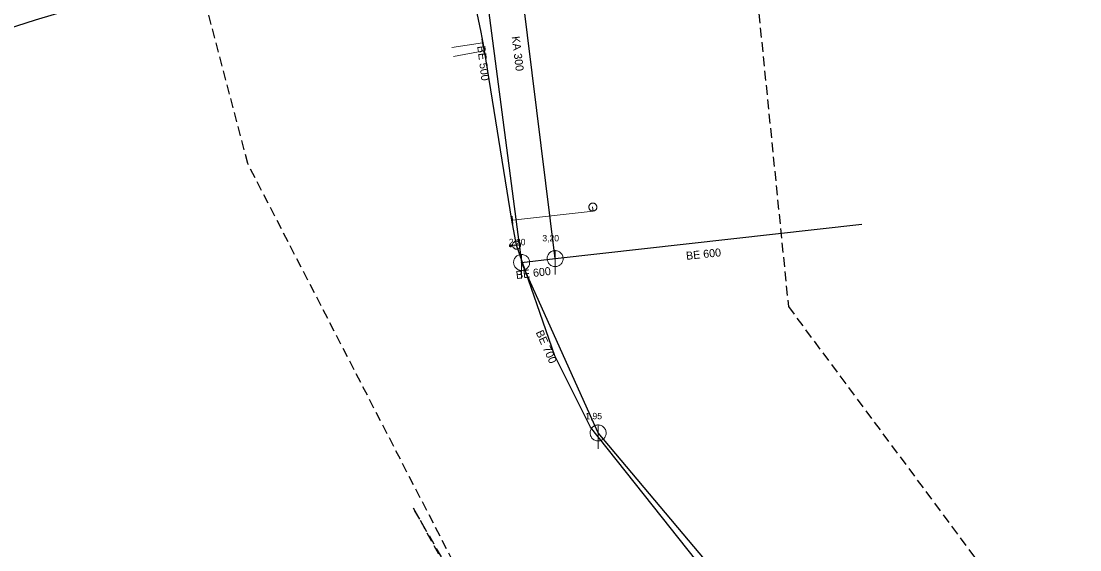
# Model space of a CAD drawing. Extents: x -689820 to -689363, y -975369 to -975062.
# Drawn here: x -689676.5 to -689544.2, y -975215.7 to -975149.6 of the extents above; entities that cross this region are included whole.
import ezdxf

# ---------------------------------------------------------------- set-up
doc = ezdxf.new("R2010")
doc.units = 0
doc.header["$LTSCALE"] = 0.4
doc.linetypes.add('MEDIUM_DASHED', pattern=[4.5, 3, -1.5])
doc.layers.add('1', color=7, linetype='Continuous')
for name, color, linetype, lineweight in [('13', 7, 'Continuous', 13), ('14', 7, 'Continuous', 25), ('17', 7, 'Continuous', 25), ('22', 7, 'Continuous', 13), ('23', 7, 'Continuous', 13), ('34', 7, 'Continuous', 13), ('47', 7, 'Continuous', 13), ('63', 7, 'MEDIUM_DASHED', 25), ('9', 7, 'Continuous', 13)]:
    doc.layers.add(name, color=color, linetype=linetype, lineweight=lineweight)

msp = doc.modelspace()

# ---------------------------------------------------------------- linework, layer by layer
at = {"layer": '13'}
for p, q in [((-689618.844, -975152.357), (-689622.676, -975152.926)), ((-689618.68, -975153.32), (-689622.456, -975154.063))]:
    msp.add_line(p, q, dxfattribs=at)
msp.add_lwpolyline([(-689615.092, -975174.481), (-689605.021, -975173.394), (-689605.076, -975172.838)], dxfattribs=at)
at = {"layer": '14'}
for p, q in [((-689609.76, -975179.3), (-689615.949, -975129.309)), ((-689620.329, -975131.18), (-689613.954, -975179.785)), ((-689609.76, -975179.3), (-689571.434, -975175.006)), ((-689613.954, -975179.785), (-689609.76, -975179.3)), ((-689604.392, -975201.087), (-689613.954, -975179.785)), ((-689553.342, -975261.657), (-689604.392, -975201.087))]:
    msp.add_line(p, q, dxfattribs=at)
at = {"layer": '14', "lineweight": 13}
for p, q in [((-689618.739, -975152.34), (-689618.844, -975152.357)), ((-689618.58, -975153.313), (-689618.68, -975153.32)), ((-689615.184, -975174.495), (-689615.092, -975174.481)), ((-689614.585, -975177.62), (-689615.339, -975177.698))]:
    msp.add_line(p, q, dxfattribs=at)
at = {"layer": '17'}
for points in [[(-689742.145, -975169.096), (-689736.511, -975167.526), (-689719.508, -975163.375), (-689716.769, -975162.653), (-689711.482, -975161.26), (-689710.52, -975160.971), (-689674.675, -975149.452), (-689666.449, -975146.987), (-689622.85, -975134.205)], [(-689614.585, -975177.62), (-689615.184, -975174.495), (-689618.58, -975153.313), (-689618.739, -975152.34), (-689619, -975151.02), (-689622.51, -975134.399)], [(-689545.213, -975278.312), (-689554.449, -975264.469), (-689605.354, -975200.364), (-689609.803, -975191.467), (-689614.585, -975177.62)]]:
    msp.add_lwpolyline(points, dxfattribs=at)
at = {"layer": '22'}
for p, q in [((-689609.76, -975181.3), (-689609.759, -975178.3)), ((-689613.954, -975181.785), (-689613.953, -975178.785)), ((-689604.392, -975203.087), (-689604.391, -975200.087))]:
    msp.add_line(p, q, dxfattribs=at)
for points in [[(-689608.76, -975179.3), (-689608.765, -975179.191), (-689608.783, -975179.083), (-689608.813, -975178.977), (-689608.853, -975178.876), (-689608.905, -975178.779), (-689608.967, -975178.689), (-689609.039, -975178.606), (-689609.119, -975178.532), (-689609.207, -975178.466), (-689609.301, -975178.411), (-689609.401, -975178.366), (-689609.506, -975178.333), (-689609.613, -975178.311), (-689609.722, -975178.301), (-689609.832, -975178.303), (-689609.94, -975178.317), (-689610.047, -975178.342), (-689610.15, -975178.379), (-689610.248, -975178.428), (-689610.34, -975178.486), (-689610.426, -975178.555), (-689610.503, -975178.632), (-689610.572, -975178.718), (-689610.631, -975178.81), (-689610.679, -975178.908), (-689610.716, -975179.011), (-689610.742, -975179.118), (-689610.756, -975179.226), (-689610.759, -975179.336), (-689610.749, -975179.445), (-689610.728, -975179.552), (-689610.694, -975179.656), (-689610.65, -975179.756), (-689610.595, -975179.851), (-689610.529, -975179.939), (-689610.455, -975180.019), (-689610.372, -975180.091), (-689610.282, -975180.153), (-689610.186, -975180.205), (-689610.084, -975180.246), (-689609.979, -975180.276), (-689609.871, -975180.294), (-689609.761, -975180.3), (-689609.652, -975180.294), (-689609.544, -975180.276), (-689609.439, -975180.247), (-689609.337, -975180.206), (-689609.24, -975180.154), (-689609.15, -975180.092), (-689609.067, -975180.021), (-689608.992, -975179.941), (-689608.927, -975179.853), (-689608.871, -975179.759), (-689608.827, -975179.659), (-689608.793, -975179.555), (-689608.771, -975179.447), (-689608.761, -975179.338)], [(-689612.954, -975179.785), (-689612.959, -975179.676), (-689612.977, -975179.568), (-689613.007, -975179.462), (-689613.047, -975179.361), (-689613.099, -975179.264), (-689613.161, -975179.174), (-689613.233, -975179.091), (-689613.313, -975179.017), (-689613.401, -975178.951), (-689613.495, -975178.896), (-689613.595, -975178.851), (-689613.7, -975178.818), (-689613.807, -975178.796), (-689613.916, -975178.786), (-689614.026, -975178.788), (-689614.134, -975178.802), (-689614.241, -975178.827), (-689614.344, -975178.864), (-689614.442, -975178.913), (-689614.534, -975178.971), (-689614.62, -975179.04), (-689614.697, -975179.117), (-689614.766, -975179.203), (-689614.825, -975179.295), (-689614.873, -975179.393), (-689614.91, -975179.496), (-689614.936, -975179.603), (-689614.95, -975179.711), (-689614.953, -975179.821), (-689614.943, -975179.93), (-689614.922, -975180.037), (-689614.888, -975180.141), (-689614.844, -975180.241), (-689614.789, -975180.336), (-689614.723, -975180.424), (-689614.649, -975180.504), (-689614.566, -975180.576), (-689614.476, -975180.638), (-689614.38, -975180.69), (-689614.278, -975180.731), (-689614.173, -975180.761), (-689614.065, -975180.779), (-689613.955, -975180.785), (-689613.846, -975180.779), (-689613.738, -975180.761), (-689613.633, -975180.732), (-689613.531, -975180.691), (-689613.434, -975180.639), (-689613.344, -975180.577), (-689613.261, -975180.506), (-689613.186, -975180.426), (-689613.121, -975180.338), (-689613.065, -975180.244), (-689613.021, -975180.144), (-689612.987, -975180.04), (-689612.965, -975179.932), (-689612.955, -975179.823)], [(-689603.392, -975201.087), (-689603.397, -975200.978), (-689603.415, -975200.87), (-689603.445, -975200.764), (-689603.485, -975200.663), (-689603.537, -975200.566), (-689603.599, -975200.476), (-689603.671, -975200.393), (-689603.751, -975200.319), (-689603.839, -975200.253), (-689603.933, -975200.198), (-689604.033, -975200.153), (-689604.138, -975200.12), (-689604.245, -975200.098), (-689604.354, -975200.088), (-689604.464, -975200.09), (-689604.572, -975200.104), (-689604.679, -975200.129), (-689604.782, -975200.166), (-689604.88, -975200.215), (-689604.972, -975200.273), (-689605.058, -975200.342), (-689605.135, -975200.419), (-689605.204, -975200.505), (-689605.263, -975200.597), (-689605.311, -975200.695), (-689605.348, -975200.798), (-689605.374, -975200.905), (-689605.388, -975201.013), (-689605.391, -975201.123), (-689605.381, -975201.232), (-689605.36, -975201.339), (-689605.326, -975201.443), (-689605.282, -975201.543), (-689605.227, -975201.638), (-689605.161, -975201.726), (-689605.087, -975201.806), (-689605.004, -975201.878), (-689604.914, -975201.94), (-689604.818, -975201.992), (-689604.716, -975202.033), (-689604.611, -975202.063), (-689604.503, -975202.081), (-689604.393, -975202.087), (-689604.284, -975202.081), (-689604.176, -975202.063), (-689604.071, -975202.034), (-689603.969, -975201.993), (-689603.872, -975201.941), (-689603.782, -975201.879), (-689603.699, -975201.808), (-689603.624, -975201.728), (-689603.559, -975201.64), (-689603.503, -975201.546), (-689603.459, -975201.446), (-689603.425, -975201.342), (-689603.403, -975201.234), (-689603.393, -975201.125)]]:
    msp.add_lwpolyline(points, close=True, dxfattribs=at)
at = {"layer": '23'}
for points in [[(-689604.616, -975173.105), (-689604.593, -975173.06), (-689604.574, -975173.009), (-689604.56, -975172.96), (-689604.554, -975172.907), (-689604.552, -975172.855), (-689604.554, -975172.803), (-689604.563, -975172.752), (-689604.576, -975172.701), (-689604.595, -975172.652), (-689604.62, -975172.606), (-689604.648, -975172.562), (-689604.68, -975172.522), (-689604.719, -975172.485), (-689604.759, -975172.452), (-689604.803, -975172.424), (-689604.85, -975172.4), (-689604.899, -975172.382), (-689604.95, -975172.369), (-689605.002, -975172.362), (-689605.054, -975172.359), (-689605.106, -975172.361), (-689605.158, -975172.369), (-689605.209, -975172.384), (-689605.256, -975172.403), (-689605.303, -975172.427), (-689605.346, -975172.456), (-689605.387, -975172.49), (-689605.424, -975172.527), (-689605.456, -975172.567), (-689605.485, -975172.611), (-689605.508, -975172.658), (-689605.527, -975172.707), (-689605.54, -975172.758), (-689605.548, -975172.809), (-689605.55, -975172.861), (-689605.548, -975172.913), (-689605.538, -975172.966), (-689605.526, -975173.015), (-689605.505, -975173.065)], [(-689605.106, -975172.361), (-689605.158, -975172.369), (-689605.209, -975172.384), (-689605.256, -975172.403), (-689605.303, -975172.427), (-689605.346, -975172.456), (-689605.387, -975172.49), (-689605.424, -975172.527), (-689605.456, -975172.567), (-689605.485, -975172.611), (-689605.508, -975172.658), (-689605.527, -975172.707), (-689605.54, -975172.758), (-689605.548, -975172.809), (-689605.55, -975172.861), (-689605.548, -975172.913), (-689605.538, -975172.966), (-689605.526, -975173.015), (-689605.505, -975173.065), (-689605.483, -975173.11), (-689605.454, -975173.155), (-689605.419, -975173.195), (-689605.382, -975173.232), (-689605.341, -975173.265), (-689605.298, -975173.294), (-689605.251, -975173.316), (-689605.201, -975173.334), (-689605.152, -975173.348), (-689605.1, -975173.355), (-689605.047, -975173.357), (-689604.995, -975173.355), (-689604.944, -975173.347), (-689604.893, -975173.333), (-689604.843, -975173.314), (-689604.798, -975173.29), (-689604.755, -975173.261), (-689604.714, -975173.228), (-689604.677, -975173.191), (-689604.644, -975173.149), (-689604.616, -975173.105)], [(-689605.505, -975173.065), (-689605.483, -975173.11), (-689605.454, -975173.155), (-689605.419, -975173.195), (-689605.382, -975173.232), (-689605.341, -975173.265), (-689605.298, -975173.294), (-689605.251, -975173.316), (-689605.201, -975173.334), (-689605.152, -975173.348), (-689605.1, -975173.355), (-689605.047, -975173.357), (-689604.995, -975173.355), (-689604.944, -975173.347), (-689604.893, -975173.333), (-689604.843, -975173.314), (-689604.798, -975173.29), (-689604.755, -975173.261), (-689604.714, -975173.228), (-689604.677, -975173.191), (-689604.644, -975173.149), (-689604.616, -975173.105), (-689604.593, -975173.06), (-689604.574, -975173.009), (-689604.56, -975172.96), (-689604.554, -975172.907), (-689604.552, -975172.855), (-689604.554, -975172.803), (-689604.563, -975172.752), (-689604.576, -975172.701), (-689604.595, -975172.652), (-689604.62, -975172.606), (-689604.648, -975172.562), (-689604.68, -975172.522), (-689604.719, -975172.485), (-689604.759, -975172.452), (-689604.803, -975172.424), (-689604.85, -975172.4), (-689604.899, -975172.382), (-689604.95, -975172.369)], [(-689604.95, -975172.369), (-689605.002, -975172.362), (-689605.054, -975172.359), (-689605.106, -975172.361)]]:
    msp.add_lwpolyline(points, dxfattribs=at)
at = {"layer": '34'}
for p, q in [((-689618.762, -975152.85), (-689618.924, -975151.863)), ((-689618.646, -975153.818), (-689618.712, -975152.821)), ((-689615.146, -975173.983), (-689615.038, -975174.978))]:
    msp.add_line(p, q, dxfattribs=at)
at = {"layer": '47'}
for points in [[(-689614.56, -975177.12), (-689614.612, -975177.121), (-689614.665, -975177.126), (-689614.715, -975177.138), (-689614.765, -975177.153), (-689614.813, -975177.175), (-689614.858, -975177.202), (-689614.9, -975177.233), (-689614.939, -975177.268), (-689614.974, -975177.306), (-689615.005, -975177.349), (-689615.031, -975177.394), (-689615.051, -975177.443), (-689615.068, -975177.492), (-689615.078, -975177.543), (-689615.084, -975177.595), (-689615.083, -975177.647), (-689615.078, -975177.7), (-689615.066, -975177.751), (-689615.051, -975177.8), (-689615.029, -975177.848), (-689615.002, -975177.893), (-689614.971, -975177.936), (-689614.936, -975177.975), (-689614.898, -975178.01), (-689614.855, -975178.04), (-689614.81, -975178.066), (-689614.762, -975178.087), (-689614.712, -975178.103), (-689614.661, -975178.113), (-689614.609, -975178.119), (-689614.557, -975178.118), (-689614.504, -975178.113), (-689614.453, -975178.102), (-689614.404, -975178.086), (-689614.356, -975178.064), (-689614.311, -975178.038), (-689614.268, -975178.007), (-689614.229, -975177.972), (-689614.194, -975177.933), (-689614.164, -975177.89), (-689614.138, -975177.845), (-689614.117, -975177.798), (-689614.101, -975177.747), (-689614.091, -975177.696), (-689614.085, -975177.644), (-689614.086, -975177.592), (-689614.091, -975177.539), (-689614.102, -975177.489), (-689614.118, -975177.439), (-689614.14, -975177.391), (-689614.166, -975177.346), (-689614.197, -975177.304), (-689614.232, -975177.265), (-689614.271, -975177.23), (-689614.314, -975177.199), (-689614.359, -975177.173), (-689614.407, -975177.153), (-689614.457, -975177.136), (-689614.508, -975177.126)], [(-689614.581, -975177.538), (-689614.589, -975177.537), (-689614.598, -975177.539), (-689614.606, -975177.54), (-689614.614, -975177.543), (-689614.622, -975177.547), (-689614.629, -975177.551), (-689614.636, -975177.556), (-689614.643, -975177.562), (-689614.648, -975177.568), (-689614.653, -975177.575), (-689614.658, -975177.583), (-689614.661, -975177.591), (-689614.664, -975177.599), (-689614.666, -975177.607), (-689614.666, -975177.616), (-689614.667, -975177.624), (-689614.665, -975177.633), (-689614.664, -975177.641), (-689614.661, -975177.649), (-689614.657, -975177.657), (-689614.653, -975177.664), (-689614.648, -975177.671), (-689614.642, -975177.678), (-689614.636, -975177.684), (-689614.629, -975177.688), (-689614.621, -975177.693), (-689614.613, -975177.696), (-689614.605, -975177.699), (-689614.597, -975177.701), (-689614.588, -975177.701), (-689614.58, -975177.702), (-689614.571, -975177.7), (-689614.563, -975177.699), (-689614.555, -975177.696), (-689614.547, -975177.692), (-689614.54, -975177.689), (-689614.533, -975177.683), (-689614.526, -975177.677), (-689614.52, -975177.671), (-689614.516, -975177.664), (-689614.511, -975177.656), (-689614.508, -975177.648), (-689614.505, -975177.64), (-689614.503, -975177.632), (-689614.503, -975177.623), (-689614.502, -975177.615), (-689614.504, -975177.606), (-689614.505, -975177.598), (-689614.508, -975177.59), (-689614.512, -975177.582), (-689614.515, -975177.575), (-689614.521, -975177.568), (-689614.527, -975177.561), (-689614.533, -975177.556), (-689614.54, -975177.551), (-689614.548, -975177.546), (-689614.556, -975177.543), (-689614.564, -975177.54), (-689614.572, -975177.538)]]:
    msp.add_lwpolyline(points, close=True, dxfattribs=at)
at = {"layer": '63'}
msp.add_lwpolyline([(-689662.123, -975114.404), (-689588.993, -975102.123), (-689588.993, -975102.123), (-689580.62, -975185.301), (-689580.62, -975185.301), (-689519.213, -975267.921), (-689519.213, -975267.921), (-689394.167, -975240.009), (-689394.167, -975240.009), (-689384.677, -975282.435), (-689384.677, -975282.435), (-689764.282, -975341.609), (-689764.282, -975341.609), (-689752.559, -975296.95), (-689752.559, -975296.95), (-689602.391, -975253.965), (-689627.512, -975210.422), (-689603.508, -975253.965), (-689648.167, -975167.437), (-689648.167, -975167.437)], close=True, dxfattribs=at)
at = {"layer": '9'}
for points in [[(-689615.465, -975177.698), (-689615.465, -975177.711), (-689615.463, -975177.724), (-689615.46, -975177.737), (-689615.455, -975177.749), (-689615.449, -975177.761), (-689615.442, -975177.772), (-689615.434, -975177.782), (-689615.424, -975177.792), (-689615.414, -975177.8), (-689615.403, -975177.807), (-689615.391, -975177.813), (-689615.379, -975177.818), (-689615.366, -975177.821), (-689615.353, -975177.823), (-689615.34, -975177.825), (-689615.327, -975177.824), (-689615.314, -975177.822), (-689615.301, -975177.819), (-689615.289, -975177.814), (-689615.277, -975177.808), (-689615.266, -975177.801), (-689615.256, -975177.793), (-689615.246, -975177.783), (-689615.238, -975177.773), (-689615.231, -975177.762), (-689615.225, -975177.75), (-689615.22, -975177.738), (-689615.217, -975177.725), (-689615.215, -975177.712), (-689615.213, -975177.699), (-689615.214, -975177.686), (-689615.216, -975177.673), (-689615.219, -975177.66), (-689615.224, -975177.648), (-689615.23, -975177.636), (-689615.237, -975177.625), (-689615.245, -975177.615), (-689615.255, -975177.605), (-689615.265, -975177.597), (-689615.276, -975177.59), (-689615.288, -975177.584), (-689615.3, -975177.579), (-689615.313, -975177.576), (-689615.326, -975177.574), (-689615.339, -975177.573), (-689615.352, -975177.573), (-689615.365, -975177.575), (-689615.378, -975177.578), (-689615.39, -975177.583), (-689615.402, -975177.589), (-689615.413, -975177.596), (-689615.423, -975177.604), (-689615.433, -975177.614), (-689615.441, -975177.624), (-689615.448, -975177.635), (-689615.454, -975177.647), (-689615.459, -975177.659), (-689615.462, -975177.672), (-689615.464, -975177.685)], [(-689615.445, -975177.698), (-689615.446, -975177.709), (-689615.444, -975177.72), (-689615.441, -975177.731), (-689615.437, -975177.741), (-689615.432, -975177.751), (-689615.426, -975177.76), (-689615.419, -975177.769), (-689615.411, -975177.777), (-689615.402, -975177.784), (-689615.393, -975177.79), (-689615.383, -975177.795), (-689615.373, -975177.799), (-689615.362, -975177.802), (-689615.351, -975177.805), (-689615.34, -975177.805), (-689615.329, -975177.805), (-689615.318, -975177.803), (-689615.307, -975177.8), (-689615.297, -975177.796), (-689615.287, -975177.791), (-689615.278, -975177.785), (-689615.269, -975177.778), (-689615.261, -975177.77), (-689615.254, -975177.761), (-689615.248, -975177.752), (-689615.243, -975177.742), (-689615.239, -975177.732), (-689615.236, -975177.721), (-689615.234, -975177.71), (-689615.233, -975177.699), (-689615.233, -975177.688), (-689615.235, -975177.677), (-689615.238, -975177.666), (-689615.242, -975177.656), (-689615.247, -975177.646), (-689615.253, -975177.637), (-689615.26, -975177.628), (-689615.268, -975177.62), (-689615.277, -975177.613), (-689615.286, -975177.607), (-689615.296, -975177.602), (-689615.306, -975177.598), (-689615.317, -975177.595), (-689615.328, -975177.593), (-689615.339, -975177.593), (-689615.35, -975177.592), (-689615.361, -975177.594), (-689615.372, -975177.597), (-689615.382, -975177.601), (-689615.392, -975177.606), (-689615.401, -975177.612), (-689615.41, -975177.619), (-689615.418, -975177.627), (-689615.425, -975177.636), (-689615.431, -975177.645), (-689615.436, -975177.655), (-689615.44, -975177.665), (-689615.443, -975177.676), (-689615.445, -975177.687)], [(-689615.426, -975177.698), (-689615.426, -975177.707), (-689615.425, -975177.716), (-689615.422, -975177.725), (-689615.419, -975177.733), (-689615.415, -975177.741), (-689615.41, -975177.749), (-689615.404, -975177.756), (-689615.398, -975177.762), (-689615.391, -975177.768), (-689615.383, -975177.773), (-689615.375, -975177.777), (-689615.367, -975177.78), (-689615.358, -975177.783), (-689615.349, -975177.784), (-689615.34, -975177.786), (-689615.331, -975177.785), (-689615.322, -975177.784), (-689615.313, -975177.781), (-689615.305, -975177.778), (-689615.297, -975177.774), (-689615.289, -975177.769), (-689615.282, -975177.763), (-689615.276, -975177.757), (-689615.27, -975177.75), (-689615.265, -975177.742), (-689615.261, -975177.734), (-689615.258, -975177.726), (-689615.255, -975177.717), (-689615.254, -975177.708), (-689615.252, -975177.699), (-689615.253, -975177.69), (-689615.254, -975177.681), (-689615.257, -975177.672), (-689615.26, -975177.664), (-689615.264, -975177.656), (-689615.269, -975177.648), (-689615.275, -975177.641), (-689615.281, -975177.635), (-689615.288, -975177.629), (-689615.296, -975177.624), (-689615.304, -975177.62), (-689615.312, -975177.617), (-689615.321, -975177.614), (-689615.33, -975177.613), (-689615.339, -975177.612), (-689615.348, -975177.612), (-689615.357, -975177.613), (-689615.366, -975177.616), (-689615.374, -975177.619), (-689615.382, -975177.623), (-689615.39, -975177.628), (-689615.397, -975177.634), (-689615.403, -975177.64), (-689615.409, -975177.647), (-689615.414, -975177.655), (-689615.418, -975177.663), (-689615.421, -975177.671), (-689615.424, -975177.68), (-689615.425, -975177.689)], [(-689615.406, -975177.698), (-689615.406, -975177.705), (-689615.405, -975177.712), (-689615.404, -975177.719), (-689615.401, -975177.725), (-689615.398, -975177.731), (-689615.394, -975177.737), (-689615.39, -975177.743), (-689615.385, -975177.748), (-689615.379, -975177.752), (-689615.373, -975177.756), (-689615.367, -975177.759), (-689615.361, -975177.762), (-689615.354, -975177.763), (-689615.347, -975177.766), (-689615.34, -975177.766), (-689615.333, -975177.766), (-689615.326, -975177.764), (-689615.319, -975177.763), (-689615.313, -975177.76), (-689615.306, -975177.757), (-689615.301, -975177.753), (-689615.295, -975177.749), (-689615.29, -975177.744), (-689615.286, -975177.738), (-689615.282, -975177.732), (-689615.279, -975177.726), (-689615.276, -975177.72), (-689615.274, -975177.713), (-689615.273, -975177.706), (-689615.272, -975177.699), (-689615.272, -975177.692), (-689615.273, -975177.685), (-689615.275, -975177.678), (-689615.278, -975177.672), (-689615.281, -975177.665), (-689615.285, -975177.66), (-689615.289, -975177.654), (-689615.294, -975177.649), (-689615.3, -975177.645), (-689615.305, -975177.641), (-689615.312, -975177.638), (-689615.318, -975177.635), (-689615.325, -975177.633), (-689615.332, -975177.632), (-689615.339, -975177.632), (-689615.346, -975177.632), (-689615.353, -975177.632), (-689615.36, -975177.634), (-689615.366, -975177.637), (-689615.372, -975177.64), (-689615.378, -975177.644), (-689615.384, -975177.648), (-689615.389, -975177.653), (-689615.393, -975177.659), (-689615.397, -975177.664), (-689615.4, -975177.671), (-689615.403, -975177.677), (-689615.404, -975177.684), (-689615.406, -975177.691)], [(-689615.386, -975177.698), (-689615.386, -975177.703), (-689615.386, -975177.708), (-689615.385, -975177.713), (-689615.383, -975177.717), (-689615.381, -975177.722), (-689615.378, -975177.726), (-689615.375, -975177.729), (-689615.371, -975177.733), (-689615.368, -975177.736), (-689615.364, -975177.739), (-689615.359, -975177.741), (-689615.355, -975177.743), (-689615.35, -975177.744), (-689615.345, -975177.746), (-689615.34, -975177.746), (-689615.335, -975177.746), (-689615.33, -975177.745), (-689615.325, -975177.744), (-689615.321, -975177.742), (-689615.316, -975177.74), (-689615.312, -975177.737), (-689615.308, -975177.734), (-689615.305, -975177.73), (-689615.302, -975177.727), (-689615.299, -975177.723), (-689615.297, -975177.718), (-689615.295, -975177.714), (-689615.294, -975177.709), (-689615.293, -975177.704), (-689615.292, -975177.699), (-689615.292, -975177.694), (-689615.293, -975177.689), (-689615.294, -975177.684), (-689615.296, -975177.68), (-689615.298, -975177.675), (-689615.301, -975177.671), (-689615.304, -975177.667), (-689615.307, -975177.664), (-689615.311, -975177.661), (-689615.315, -975177.658), (-689615.32, -975177.656), (-689615.324, -975177.654), (-689615.329, -975177.653), (-689615.334, -975177.652), (-689615.339, -975177.652), (-689615.344, -975177.652), (-689615.349, -975177.653), (-689615.354, -975177.653), (-689615.358, -975177.655), (-689615.363, -975177.657), (-689615.367, -975177.66), (-689615.37, -975177.663), (-689615.374, -975177.666), (-689615.377, -975177.67), (-689615.38, -975177.674), (-689615.382, -975177.679), (-689615.384, -975177.683), (-689615.385, -975177.688), (-689615.386, -975177.693)], [(-689615.366, -975177.698), (-689615.366, -975177.701), (-689615.367, -975177.704), (-689615.366, -975177.706), (-689615.365, -975177.709), (-689615.364, -975177.712), (-689615.362, -975177.714), (-689615.36, -975177.716), (-689615.358, -975177.718), (-689615.356, -975177.72), (-689615.354, -975177.722), (-689615.351, -975177.724), (-689615.348, -975177.725), (-689615.346, -975177.725), (-689615.343, -975177.726), (-689615.34, -975177.726), (-689615.337, -975177.726), (-689615.334, -975177.726), (-689615.331, -975177.725), (-689615.329, -975177.724), (-689615.326, -975177.723), (-689615.324, -975177.721), (-689615.321, -975177.719), (-689615.319, -975177.717), (-689615.318, -975177.715), (-689615.316, -975177.713), (-689615.315, -975177.71), (-689615.313, -975177.707), (-689615.313, -975177.705), (-689615.312, -975177.702), (-689615.311, -975177.699), (-689615.312, -975177.696), (-689615.312, -975177.693), (-689615.313, -975177.69), (-689615.314, -975177.688), (-689615.315, -975177.685), (-689615.317, -975177.683), (-689615.318, -975177.68), (-689615.32, -975177.678), (-689615.323, -975177.677), (-689615.325, -975177.675), (-689615.328, -975177.674), (-689615.33, -975177.673), (-689615.333, -975177.672), (-689615.336, -975177.672), (-689615.339, -975177.671), (-689615.342, -975177.672), (-689615.345, -975177.671), (-689615.347, -975177.673), (-689615.35, -975177.673), (-689615.353, -975177.674), (-689615.355, -975177.676), (-689615.357, -975177.677), (-689615.359, -975177.679), (-689615.361, -975177.682), (-689615.363, -975177.684), (-689615.364, -975177.687), (-689615.365, -975177.689), (-689615.366, -975177.692), (-689615.366, -975177.695)], [(-689615.347, -975177.698), (-689615.347, -975177.7), (-689615.347, -975177.7), (-689615.346, -975177.7), (-689615.346, -975177.702), (-689615.347, -975177.703), (-689615.345, -975177.703), (-689615.345, -975177.703), (-689615.345, -975177.705), (-689615.345, -975177.705), (-689615.344, -975177.706), (-689615.342, -975177.706), (-689615.342, -975177.706), (-689615.342, -975177.707), (-689615.34, -975177.707), (-689615.34, -975177.707), (-689615.339, -975177.707), (-689615.338, -975177.707), (-689615.338, -975177.706), (-689615.337, -975177.706), (-689615.335, -975177.706), (-689615.335, -975177.705), (-689615.335, -975177.705), (-689615.334, -975177.704), (-689615.334, -975177.704), (-689615.332, -975177.703), (-689615.332, -975177.702), (-689615.331, -975177.701), (-689615.331, -975177.701), (-689615.331, -975177.7), (-689615.331, -975177.699), (-689615.331, -975177.698), (-689615.331, -975177.697), (-689615.331, -975177.697), (-689615.332, -975177.696), (-689615.332, -975177.695), (-689615.333, -975177.694), (-689615.333, -975177.694), (-689615.334, -975177.693), (-689615.334, -975177.693), (-689615.335, -975177.692), (-689615.336, -975177.692), (-689615.337, -975177.691), (-689615.337, -975177.691), (-689615.338, -975177.691), (-689615.339, -975177.691), (-689615.34, -975177.691), (-689615.341, -975177.691), (-689615.341, -975177.691), (-689615.342, -975177.692), (-689615.343, -975177.691), (-689615.344, -975177.693), (-689615.344, -975177.693), (-689615.345, -975177.693), (-689615.345, -975177.693), (-689615.346, -975177.695), (-689615.346, -975177.696), (-689615.346, -975177.697), (-689615.347, -975177.697), (-689615.347, -975177.698)]]:
    msp.add_lwpolyline(points, close=True, dxfattribs=at)

# ---------------------------------------------------------------- texts
at = {"layer": '1'}
for s, rotation, p in [('KA 300', 277, (-689615.193, -975151.571)), ('BE 500', 277, (-689619.499, -975152.766)), ('BE 600', 6, (-689593.356, -975179.459)), ('BE 600', 7, (-689614.608, -975181.859)), ('BE 700', 294, (-689612.211, -975188.511))]:
    msp.add_text(s, height=1, rotation=rotation, dxfattribs=at).set_placement(p)
for s, p in [('2,20', (-689615.554, -975177.633)), ('3,20', (-689611.359, -975177.147)), ('1,95', (-689605.992, -975199.375))]:
    msp.add_text(s, height=0.8, dxfattribs=at).set_placement(p)

doc.saveas('drawing.dxf')
